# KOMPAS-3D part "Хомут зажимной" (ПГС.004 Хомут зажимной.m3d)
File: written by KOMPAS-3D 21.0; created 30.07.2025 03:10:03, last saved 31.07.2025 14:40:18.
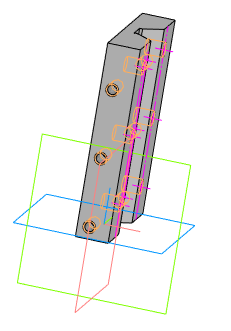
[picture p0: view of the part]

Document properties: Автор: rinat.gaysin.00@bk.ru; Полное имя файла: C:\Users\User\Desktop\ПЕРСПЕКТИВА кд\Модель\ПГС.004 Хомут зажимной.m3d

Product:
- Part/product: Хомут зажимной
    Масса: 0.237292
    Форматы листов документа: A3

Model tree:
1. Эскиз:1
2. Элемент выдавливания:1
     Расстояние 1 = 65
3. Эскиз:2  (with: Элемент выдавливания:1)
4. Отверстие:1  (with: Элемент выдавливания:1)  (labels: M5)
     Глубина выреза = 8; Диаметр отверстия = 4.13397; Угол конуса дна = 118; Расстояние 1 = 57; Расстояние 2 = 5.4
5. M5  (with: Элемент выдавливания:1)  (labels: cil0_24705-2004 coarse)
     Длина резьбы = 6; Шаг резьбы = 0.8; Номинальный диаметр резьбы = 5
6. Массив по точкам:1
7. Экземпляр ( 3 )  (with: Отверстие:1, Эскиз:2)  (labels: M5)
8. Экземпляр ( 1 )  (with: Отверстие:1, Эскиз:2)  (labels: M5)
9. Экземпляр ( 4 )  (with: Отверстие:1, Эскиз:2)  (labels: M5)
10. Экземпляр ( 2 )  (with: Отверстие:1, Эскиз:2)  (labels: M5)
11. Экземпляр ( 5 )  (with: Отверстие:1, Эскиз:2)  (labels: M5)
12. Эскиз:3  (with: Элемент выдавливания:1)
13. Отверстие:2  (with: Элемент выдавливания:1)  (labels: M4)
     Глубина выреза = 10; Диаметр отверстия = 3.24223; Угол конуса дна = 118; Расстояние 1 = 50; Расстояние 2 = 4
14. M4  (with: Элемент выдавливания:1)  (labels: M4; cil0_24705-2004 coarse)
     Длина резьбы = 8; Шаг резьбы = 0.7; Номинальный диаметр резьбы = 4
15. Фаска:1  (with: Отверстие:1, Отверстие:2)
     Угол = 45; Длина 1 = 0.5; Длина 2 = 0.5
16. Массив по точкам:2  (with: Экземпляр ( 2 ), Отверстие:2, Эскиз:3)  (labels: M4)
17. Фаска:1  (with: Экземпляр ( 1 ), Отверстие:2, Эскиз:3)  (labels: 5␣; M4)
18. Фаска:1
19. Зеркальный массив:1  (with: Экземпляр ( 1 ), Экземпляр ( 2 ), Отверстие:2)
20. Фаска:1  (with: Массив по точкам:2, Экземпляр ( 2 ), Отверстие:2)
21. Фаска:1  (with: Экземпляр ( 1 ), Отверстие:2)
22. Фаска:1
